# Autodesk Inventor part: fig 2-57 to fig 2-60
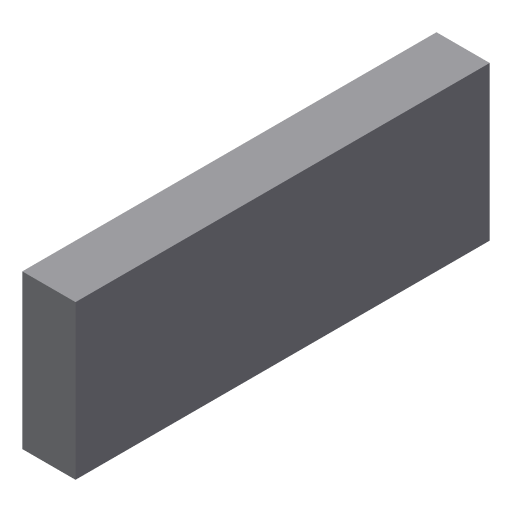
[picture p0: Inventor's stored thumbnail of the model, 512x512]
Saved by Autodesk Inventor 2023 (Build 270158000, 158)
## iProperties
Created: 2011-06
Part Number: fig 2-57 to fig 2-60
Material: Generic
Document SubType Name: Modeling
Designer: CadCim
Density: 1 g/cm^3
Appearance: Default
Author: CadCim
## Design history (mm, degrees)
sketch "Sketch1"
  geometry: 1 further point
sketch "Sketch2"
  geometry: L1 (-35, 13)-(0, 13); L2 (0, 13)-(0, 0); L3 (0, 0)-(-35, 0); L4 (-35, 0)-(-35, 13); 1 further point
  constraints: 8 end point, 2 parallel, 1 coincident, 1 horizontal, 1 perpendicular
extrude "Extrusion1" new body sketch "Sketch2" distance "d0" = 4.5; taper "d1" = 0 deg
body "Solid1"
